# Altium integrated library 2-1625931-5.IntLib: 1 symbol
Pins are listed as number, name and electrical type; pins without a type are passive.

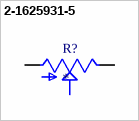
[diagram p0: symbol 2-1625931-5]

## 2-1625931-5
designator R?
100k Ohm 1 Gang Linear Panel Mount Potentiometer None 1.0 Kierros Cermet 2W PC Pins; MP: 2-1625931-5; MF: TE Connectivity
footprint TRIM_2-1625931-5
pins: 1, 2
